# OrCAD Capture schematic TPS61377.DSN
size B
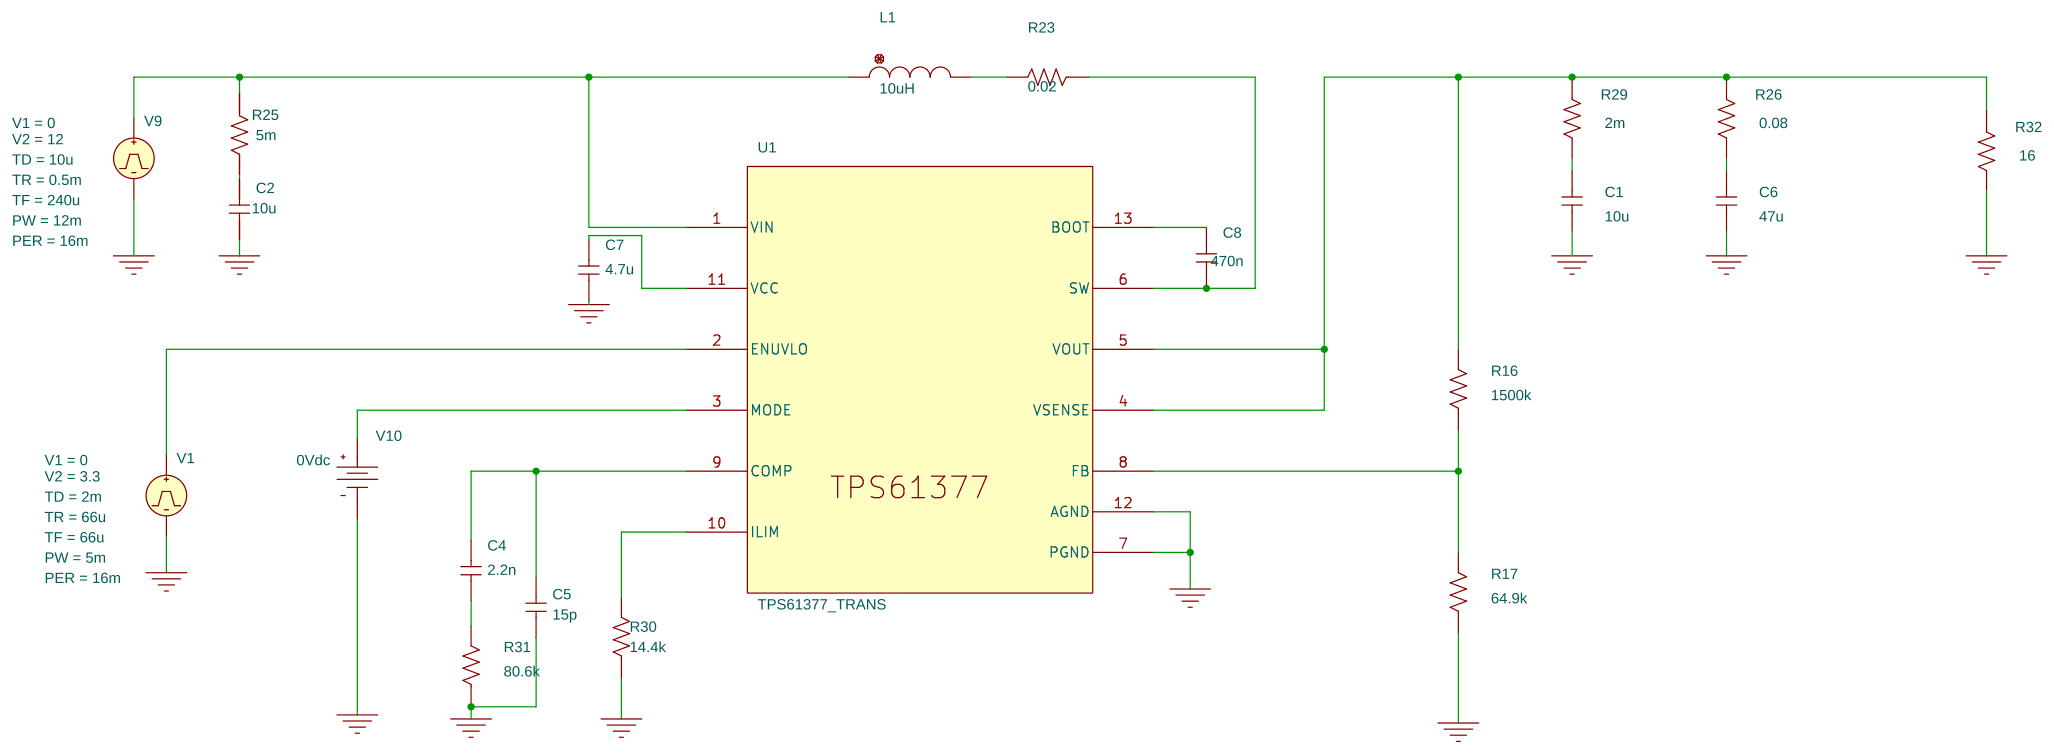
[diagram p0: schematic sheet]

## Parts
C1  10u  [cap196]
C2  10u  [cap196]
C4  2.2n  [cap196]
C5  15p  [cap196]
C6  47u  [cap196]
C7  4.7u  [cap196]
C8  470n  [cap196]
L1  10uH  [DISC350x175LS200x100034]
R16  1500k  [AX/RC05]
R17  64.9k  [AX/RC05]
R23  0.02  [AX/RC05]
R25  5m  [AX/RC05]
R26  0.08  [AX/RC05]
R29  2m  [AX/RC05]
R30  14.4k  [AX/RC05]
R31  80.6k  [AXRC05]
R32  16  [AX/RC05]
U1  TPS61377_TRANS
V1  VPULSE
V9  VPULSE
V10  VDC

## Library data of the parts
C1 C2 C4-C8 = C
L1 = L
R16 R17 R23 R25 R26 R29-R32 = R
U1 = TPS61377_SYMBOL
V1 = VPULSE: PER: 16m; PW: 5m; TD: 2m; TF: 66u; TR: 66u; V1: 0; V2: 3.3
V9 = VPULSE: PER: 16m; PW: 12m; TD: 10u; TF: 240u; TR: 0.5m; V1: 0; V2: 12
V10 = VDC: DC: 0Vdc

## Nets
0: C1.1 C2.1 C5.1 C6.1 C7.1 R17.1 R30.1 R31.1 R32.2 U1.7(PGND) U1.12(AGND) V1.2(-) V9.2(-) V10.1(-)
N29482: L1.1 R25.1 U1.1(VIN) V9.1(+)
N29512: L1.2 R23.2
N29518: C8.1 R23.1 U1.6(SW)
N29528: R16.2 R26.1 R29.1 R32.1 U1.4(VSENSE) U1.5(VOUT)
N29694: C2.2 R25.2
N29700: C1.2 R29.2
N29706: C6.2 R26.2
N29812: C8.2 U1.13(BOOT)
N29852: C7.2 U1.11(VCC)
N29952: U1.2(ENUVLO) V1.1(+)
N30012: U1.3(MODE) V10.0(+)
N30026: R16.1 R17.2 U1.8(FB)
N30074: C4.2 C5.2 U1.9(COMP)
N30150: R30.2 U1.10(ILIM)
N30194: C4.1 R31.2
